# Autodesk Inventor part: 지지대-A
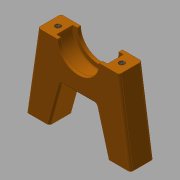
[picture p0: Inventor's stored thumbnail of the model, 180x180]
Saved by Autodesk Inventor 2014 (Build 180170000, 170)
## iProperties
Created: 2018-01
Part Number: 지지대-A
Material: 일반
Document SubType Name: Modeling
Designer: mduedu
Density: 1 g/cm^3
Appearance: 주황색
Author: mduedu
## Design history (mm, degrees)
sketch "스케치1"
  geometry: L1 (-22.5, 0)-(22.5, 0); L2 (22.5, 0)-(17.5, 34); L3 (17.5, 34)-(-17.5, 34); L4 (-17.5, 34)-(-22.5, 0); 3 further points
  constraints: 8 end point, 2 midpoint, 1 coincident, 1 horizontal, 1 parallel, 1 vertical alignment
  dimensions: "d0" = 45 distance of L1.start L1.end; "d3" = 35 distance of L2.end L3.end; "d4" = 34 vertical distance of L1.end L2.end
extrude "돌출1" new body sketch "스케치1" stored distance "d5" = 10; taper "d6" = 0 deg
sketch "스케치2"
  geometry: L1 (-12.5, 0)-(12.5, 0); L2 (12.5, 0)-(7.5, 18); L3 (7.5, 18)-(-7.5, 18); L4 (-7.5, 18)-(-12.5, 0); L5 (-22.5, 0)-(22.5, 0) reference; 4 further points
  constraints: 8 end point, 4 midpoint, 1 horizontal, 1 parallel, 1 vertical alignment
  dimensions: "d7" = 10 distance of L1.start L5.start; "d8" = 10 distance of L1.end L5.end (derived); "d9" = 15 distance of L2.end L3.end; "d10" = 18 distance between parallel lines of L1 L3
extrude "돌출2" cut sketch "스케치2" stored distance "d11" = 10; taper "d12" = 0 deg
sketch "스케치3"
  geometry: L1 (-17.5, 34)-(17.5, 34) reference; C1 r 11 at (0, 34); C2 r 9 at (0, 34); 1 further point
  constraints: 2 centre point, 1 coincident, 1 midpoint
  dimensions: "d13" = 22 diameter of C1; "d16" = 18 diameter of C2
extrude "돌출3" cut sketch "스케치3" stored distance "d14" = 7; taper "d15" = 0 deg
extrude "돌출4" cut sketch "스케치3" stored distance "d17" = 7; taper "d18" = 0 deg
fillet "모깎기1" dims "d19" = 0.3
fillet "모깎기2" dims "d20" = 1
fillet "모깎기3" dims "d21" = 1
fillet "모깎기4" dims "d22" = 1
sketch "스케치4"
  geometry: 2 further points
  constraints: 2 other
hole "구멍1" sketch "스케치4" at (-22.771, -3.5), (4.771, -3.5) diameter "d23" = 2.459; stored, may be unused: countersink angle "d27" = 90 deg, drill point angle "d29" = 120 deg; dims "d24" = 4.5, "d25" = 4, "d26" = 2, "d28" = 6
sketch "스케치5"
  geometry: 4 further points
  constraints: 4 other
hole "구멍2" sketch "스케치5" at (40, 4), (5, -27), (40, -27), (5, 4) diameter "d30" = 2.459; stored, may be unused: countersink angle "d34" = 90 deg, drill point angle "d36" = 120 deg; dims "d31" = 6.9, "d32" = 4, "d33" = 2, "d35" = 8.4
node "솔리드1"
